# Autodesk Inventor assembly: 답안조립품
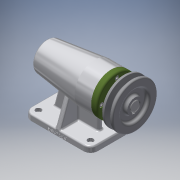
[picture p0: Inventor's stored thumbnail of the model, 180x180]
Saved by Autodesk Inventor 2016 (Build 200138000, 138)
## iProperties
Created: 2018-09
Part Number: 답안조립품
Material: 일반
Document SubType Name: Assembly
Designer: 3sil_cad018
Author: 3sil_cad018
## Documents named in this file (12)
- C:\Users\3sil_cad018\Desktop\480908V1008\답안조립품.iam
- C:\Users\3sil_cad018\Desktop\480908V1008\본체.ipt
- C:\Users\3sil_cad018\Desktop\480908V1008\V벨트풀리.ipt
- C:\Users\3sil_cad018\Desktop\480908V1008\멈춤나사 M3.ipt
- C:\Users\3sil_cad018\Desktop\480908V1008\베어링 6004.ipt
- C:\Users\3sil_cad018\Desktop\480908V1008\베어링 51202.ipt
- C:\Users\3sil_cad018\Desktop\480908V1008\볼트 M4.ipt
- C:\Users\3sil_cad018\Desktop\480908V1008\어댑터슬리브.ipt
- C:\Users\3sil_cad018\Desktop\480908V1008\오일 실.ipt
- C:\Users\3sil_cad018\Desktop\480908V1008\축.ipt
- C:\Users\3sil_cad018\Desktop\480908V1008\커버.ipt
- C:\Users\3sil_cad018\Desktop\480908V1008\키 5 x 5 x 16.ipt
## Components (1 placed, 1 different names)
1. V벨트풀리:1 — 각도:2
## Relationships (1: Angle 1)
- 각도:2 [Angle]: V벨트풀리:1
